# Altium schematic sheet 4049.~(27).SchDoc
size A4
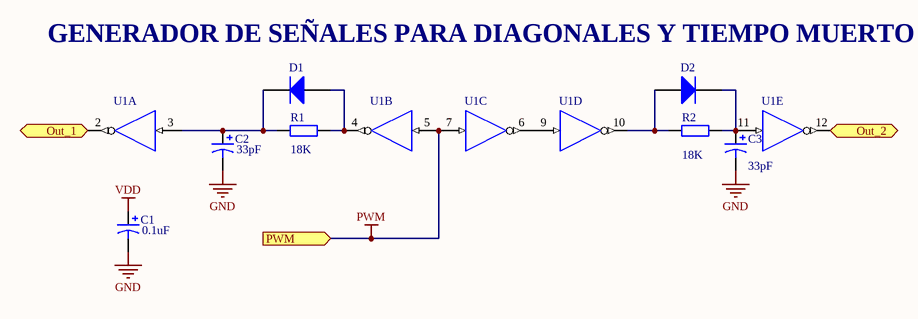
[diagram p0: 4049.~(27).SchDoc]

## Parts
C1  value 0.1uF  [CAPPR2.5-6.3X5]  (hidden comment: Cap Pol1)
C2  value 33pF  [CAPPR2.5-6.3X5]  (hidden comment: Cap Pol1)
C3  value 33pF  [CAPPR2.5-6.3X5]  (hidden comment: Cap Pol1)
D1  Diode1  [DO-204AL]  (value not drawn)
D2  Diode1  [DO-204AL]  (value not drawn)
R1  value 18K  [AXIAL-0.3]  (hidden comment: Res2)
R2  value 18K  [AXIAL-0.3]  (hidden comment: Res2)
U1  MC54HC4049J  [620-09]  (value not drawn)  (parts A,B,C,D,E of 6)

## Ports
Out_1 (out), Out_2 (out), PWM (in)

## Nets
GND: C1.2 C2.2 C3.2 U1.8(GND)
PWM: U1.5(A) U1.7(A) ; port PWM
VDD: C1.1 U1.1(VDD)
Out_1: U1.2(Y) ; port Out_1
Out_2: U1.12(Y) ; port Out_2
NetC2_1: C2.1 D1.2(K) R1.1 U1.3(A)
NetC3_1: C3.1 D2.2(K) R2.2 U1.11(A)
NetD1_1: D1.1(A) R1.2 U1.4(Y)
NetD2_1: D2.1(A) R2.1 U1.10(Y)
NetU1_6: U1.6(Y) U1.9(A)

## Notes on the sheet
- GENERADOR DE SEÑALES PARA DIAGONALES Y TIEMPO MUERTO

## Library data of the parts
C1-C3 = Cap Pol1: Polarized Capacitor (Radial)
D1 D2 = Diode: 1N4148
R1 R2 = Res2: Resistor
U1 = MC54HC4049J: Hex Inverting Buffer/Logic-Level Down Converter; Note: Pins 13 & 16 are NC and not drawn.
